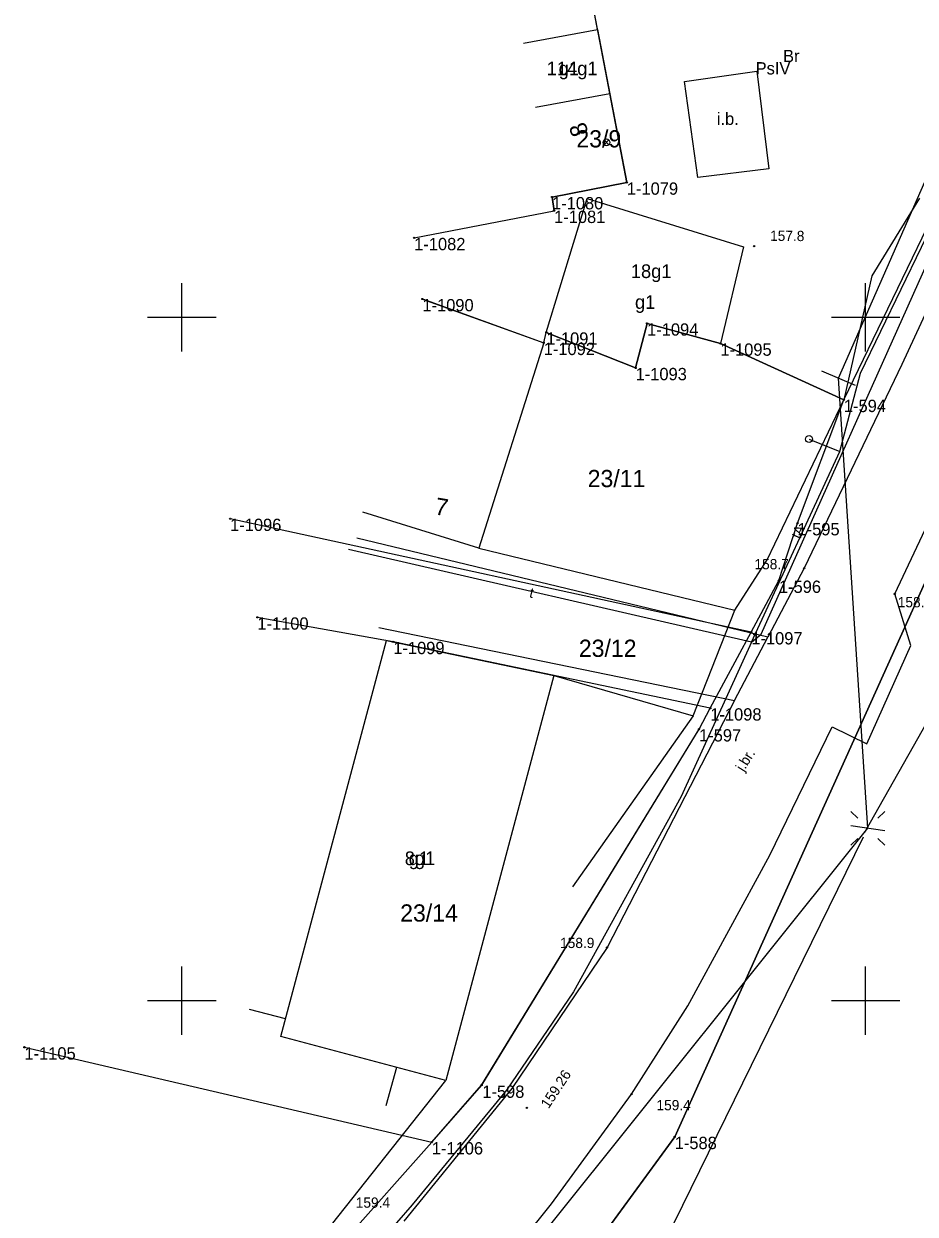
# Model space of a CAD drawing. Extents: x 5598798 to 5599616, y 5661498 to 5662453.
# Drawn here: x 5599088.4 to 5599153.6, y 5661634.4 to 5661721.5 of the extents above; entities that cross this region are included whole.
import ezdxf

# ---------------------------------------------------------------- set-up
doc = ezdxf.new("R2010")
doc.units = 0
for name, color, linetype in [('BUIB_E_T_6', 7, 'Continuous'), ('BUIB_L_1', 7, 'Continuous'), ('BUIB_L_10', 7, 'Continuous'), ('Dzialki', 7, 'Continuous'), ('EADTD_T_0', 7, 'Continuous'), ('EAPADR_T_0', 7, 'Continuous'), ('EGBB_E_T_0', 7, 'Continuous'), ('EGBB_E_T_1', 7, 'Continuous'), ('EGBB_L_0', 7, 'Continuous'), ('Kontury', 7, 'Continuous'), ('KTJZ_E_T_0', 7, 'Continuous'), ('KTJZ_L_0', 7, 'Continuous'), ('KTOK_L_1', 7, 'Continuous'), ('KTOK_L_4', 7, 'Continuous'), ('Numery_dzialek', 7, 'Continuous'), ('Numery_konturow', 7, 'Continuous'), ('Numery_punktow', 7, 'Continuous'), ('Numery_uzytkow', 7, 'Continuous'), ('Podzial_sekcyjny_krzyze', 7, 'Continuous'), ('Punkty', 7, 'Continuous'), ('RTPW_T_0', 7, 'Continuous'), ('RTPW_T_1', 7, 'Continuous'), ('SUPE_L_3', 7, 'Continuous'), ('SUPT_E_T_0', 7, 'Continuous'), ('SUPT_L_0', 7, 'Continuous'), ('SUSM_L_4', 7, 'Continuous'), ('SUSM_T_0', 7, 'Continuous'), ('SUSM_T_3', 7, 'Continuous'), ('Uzytki', 7, 'Continuous')]:
    doc.layers.add(name, color=color, linetype=linetype)

# ---------------------------------------------------------------- blocks, each defined once
blk = doc.blocks.new('GRO')
blk.add_circle((0, 0), 0.045)
blk = doc.blocks.new('1_PADR')
for p, q in [((-0.17675, -0.17675), (0.17675, 0.17675)), ((0.17675, -0.17675), (-0.17675, 0.17675))]:
    blk.add_line(p, q)
blk.add_circle((0, 0), 0.25)
blk = doc.blocks.new('2_RTPW01')
blk.add_circle((0, 0), 0.045)
blk = doc.blocks.new('2_RTPW02')
blk.add_circle((0, 0), 0.045)
blk = doc.blocks.new('4_SUSM01_01')
for p, q in [((-0.74249, 0.74249), (-1.23746, 1.23746)), ((0.74249, 0.74249), (1.23746, 1.23746)), ((-0.74249, -0.74249), (-1.23746, -1.23746)), ((0.74249, -0.74249), (1.23746, -1.23746))]:
    blk.add_line(p, q)
blk = doc.blocks.new('4_SUSM04_01')
blk.add_circle((0, 0), 0.25)

msp = doc.modelspace()

# ---------------------------------------------------------------- linework, layer by layer
at = {"layer": 'BUIB_L_1'}
for p, q in [((5599107.586968, 5661648.68043), (5599104.937907, 5661649.356613)), ((5599115.696576, 5661645.112289), (5599114.918825, 5661642.299391))]:
    msp.add_line(p, q, dxfattribs=at)
at = {"layer": 'BUIB_L_10'}
for p, q in [((5599136.765384, 5661717.245894), (5599142.040119, 5661717.989979)), ((5599137.740962, 5661710.218425), (5599136.765384, 5661717.245894)), ((5599142.040119, 5661717.989979), (5599142.921998, 5661710.852276)), ((5599142.921998, 5661710.852276), (5599137.740962, 5661710.218425)), ((5599149.83, 5661661.97), (5599133.66, 5661629))]:
    msp.add_line(p, q, dxfattribs=at)
at = {"layer": 'Dzialki'}
for p, q in [((5599148.41, 5661693.96), (5599172.35, 5661743.59)), ((5599132.54, 5661709.86), (5599128.89, 5661728.95)), ((5599127.07, 5661708.79), (5599132.54, 5661709.86)), ((5599127.22, 5661707.79), (5599127.07, 5661708.79)), ((5599116.99, 5661705.8), (5599127.22, 5661707.79)), ((5599117.59, 5661701.33), (5599126.46, 5661698.13)), ((5599126.46, 5661698.13), (5599126.65, 5661698.89)), ((5599126.65, 5661698.89), (5599133.18, 5661696.29)), ((5599133.18, 5661696.29), (5599134.02, 5661699.55)), ((5599134.02, 5661699.55), (5599139.38, 5661698.08)), ((5599139.38, 5661698.08), (5599148.41, 5661693.96)), ((5599145.02, 5661684.94), (5599148.41, 5661693.96)), ((5599141.64, 5661676.96), (5599103.53, 5661685.26)), ((5599143.66, 5661680.73), (5599145.02, 5661684.94)), ((5599155.84, 5661683.95), (5599136.04, 5661640.04)), ((5599141.64, 5661676.96), (5599143.66, 5661680.73)), ((5599115.46, 5661676.25), (5599105.52, 5661678.04)), ((5599138.64, 5661671.39), (5599115.46, 5661676.25)), ((5599138.64, 5661671.39), (5599141.64, 5661676.96)), ((5599137.82, 5661669.86), (5599138.64, 5661671.39)), ((5599121.922727, 5661643.823565), (5599137.82, 5661669.86)), ((5599088.49, 5661646.59), (5599118.28, 5661639.65)), ((5599118.28, 5661639.65), (5599121.922727, 5661643.823565)), ((5599106.61, 5661626.54), (5599118.28, 5661639.65)), ((5599136.04, 5661640.04), (5599129.55, 5661631.14))]:
    msp.add_line(p, q, dxfattribs=at)
at = {"layer": 'EGBB_L_0'}
for p, q in [((5599130.402266, 5661721.050548), (5599128.89, 5661728.95)), ((5599124.98595, 5661720.056186), (5599130.402266, 5661721.050548)), ((5599130.402266, 5661721.050548), (5599131.294836, 5661716.348368)), ((5599131.294836, 5661716.348368), (5599125.850628, 5661715.345187)), ((5599131.294836, 5661716.348368), (5599132.54, 5661709.86)), ((5599132.54, 5661709.86), (5599127.07, 5661708.79)), ((5599126.65, 5661698.89), (5599129.644169, 5661708.695065)), ((5599127.07, 5661708.79), (5599127.22, 5661707.79)), ((5599129.644169, 5661708.695065), (5599141.079379, 5661705.157254)), ((5599116.99, 5661705.8), (5599127.22, 5661707.79)), ((5599141.079379, 5661705.157254), (5599139.38, 5661698.08)), ((5599117.593221, 5661701.334271), (5599126.46, 5661698.13)), ((5599133.18, 5661696.29), (5599126.65, 5661698.89)), ((5599134.02, 5661699.55), (5599133.18, 5661696.29)), ((5599139.38, 5661698.08), (5599134.02, 5661699.55)), ((5599126.46, 5661698.13), (5599121.728162, 5661683.10618)), ((5599121.728162, 5661683.10618), (5599113.227989, 5661685.736155)), ((5599107.236944, 5661647.366337), (5599114.955347, 5661676.343468)), ((5599114.955347, 5661676.343468), (5599127.190146, 5661673.791932)), ((5599127.190146, 5661673.791932), (5599119.296241, 5661644.153167)), ((5599119.296241, 5661644.153167), (5599107.236944, 5661647.366337))]:
    msp.add_line(p, q, dxfattribs=at)
at = {"layer": 'Kontury'}
for p, q in [((5599148.41, 5661693.96), (5599172.35, 5661743.59)), ((5599145.02, 5661684.94), (5599148.41, 5661693.96)), ((5599143.66, 5661680.73), (5599145.02, 5661684.94)), ((5599136.04, 5661640.04), (5599155.84, 5661683.95)), ((5599141.64, 5661676.96), (5599143.66, 5661680.73)), ((5599138.64, 5661671.39), (5599141.64, 5661676.96)), ((5599137.82, 5661669.86), (5599138.64, 5661671.39)), ((5599121.922727, 5661643.823565), (5599137.82, 5661669.86)), ((5599118.28, 5661639.65), (5599121.922727, 5661643.823565)), ((5599106.61, 5661626.54), (5599118.28, 5661639.65)), ((5599129.55, 5661631.14), (5599136.04, 5661640.04))]:
    msp.add_line(p, q, dxfattribs=at)
at = {"layer": 'KTJZ_L_0'}
for p, q in [((5599161.82, 5661716.42), (5599152.64, 5661696.54)), ((5599152.13, 5661679.75), (5599161.53, 5661699.74)), ((5599152.64, 5661696.54), (5599145.51, 5661681.63)), ((5599142.85, 5661676.59), (5599112.8, 5661683.84)), ((5599145.51, 5661681.63), (5599142.85, 5661676.59)), ((5599153.3, 5661675.98), (5599152.13, 5661679.75)), ((5599114.41, 5661677.3), (5599140.4, 5661671.95)), ((5599140.4, 5661671.95), (5599142.85, 5661676.59)), ((5599150.08, 5661668.78), (5599153.3, 5661675.98)), ((5599140.4, 5661671.95), (5599131.09, 5661653.89)), ((5599142.99, 5661660.65), (5599147.56, 5661670.04)), ((5599147.56, 5661670.04), (5599150.08, 5661668.78)), ((5599136.99, 5661649.62), (5599142.99, 5661660.65)), ((5599131.09, 5661653.89), (5599124.14, 5661643.58)), ((5599132.88, 5661643.17), (5599136.99, 5661649.62)), ((5599124.14, 5661643.58), (5599116.23, 5661633.87)), ((5599127.02, 5661635.13), (5599132.88, 5661643.17)), ((5599122.86, 5661629.96), (5599127.02, 5661635.13))]:
    msp.add_line(p, q, dxfattribs=at)
at = {"layer": 'KTOK_L_1'}
msp.add_line((5599137.397412, 5661670.82674), (5599140.428869, 5661678.570734), dxfattribs=at)
at = {"layer": 'KTOK_L_4'}
for p, q in [((5599153.946801, 5661708.707327), (5599150.463381, 5661703.019211)), ((5599150.463381, 5661703.019211), (5599148.41, 5661693.96)), ((5599148.41, 5661693.96), (5599139.38, 5661698.08)), ((5599142.812449, 5661682.251695), (5599148.41, 5661693.96)), ((5599121.728162, 5661683.10618), (5599140.428869, 5661678.570734)), ((5599140.428869, 5661678.570734), (5599142.812449, 5661682.251695)), ((5599127.190146, 5661673.791932), (5599137.397412, 5661670.82674)), ((5599137.397412, 5661670.82674), (5599128.555341, 5661658.319499)), ((5599106.208386, 5661627.645012), (5599119.296241, 5661644.153167))]:
    msp.add_line(p, q, dxfattribs=at)
at = {"layer": 'Podzial_sekcyjny_krzyze'}
for p, q in [((5599100, 5661697.5), (5599100, 5661702.5)), ((5599150, 5661697.5), (5599150, 5661702.5)), ((5599097.5, 5661700), (5599102.5, 5661700)), ((5599147.5, 5661700), (5599152.5, 5661700)), ((5599100, 5661647.5), (5599100, 5661652.5)), ((5599150, 5661647.5), (5599150, 5661652.5)), ((5599097.5, 5661650), (5599102.5, 5661650)), ((5599147.5, 5661650), (5599152.5, 5661650))]:
    msp.add_line(p, q, dxfattribs=at)
at = {"layer": 'SUPE_L_3'}
for p, q in [((5599148.021884, 5661695.534034), (5599158.332094, 5661719.064332)), ((5599150.160871, 5661662.612128), (5599148.021884, 5661695.534034)), ((5599160.846586, 5661681.673946), (5599149.92, 5661662.3)), ((5599125.304463, 5661631.572851), (5599150.160871, 5661662.612128))]:
    msp.add_line(p, q, dxfattribs=at)
at = {"layer": 'SUPT_L_0'}
for p, q in [((5599149.624419, 5661695.89561), (5599157.421027, 5661712.050333)), ((5599142.364839, 5661676.801704), (5599155.313425, 5661705.739483)), ((5599148.123603, 5661690.178824), (5599149.624419, 5661695.89561)), ((5599145.861892, 5661691.087872), (5599148.123603, 5661690.178824)), ((5599141.657376, 5661676.235365), (5599148.123603, 5661690.178824)), ((5599141.657376, 5661676.235365), (5599112.179701, 5661683.008901)), ((5599141.657376, 5661676.235365), (5599136.511984, 5661664.923152)), ((5599141.657376, 5661676.235365), (5599142.364839, 5661676.801704)), ((5599136.511984, 5661664.923152), (5599128.632872, 5661650.637436)), ((5599128.632872, 5661650.637436), (5599123.734045, 5661643.442762)), ((5599123.734045, 5661643.442762), (5599116.831229, 5661635.062005)), ((5599116.831229, 5661635.062005), (5599109.40253, 5661626.489212))]:
    msp.add_line(p, q, dxfattribs=at)
at = {"layer": 'SUSM_L_4'}
for p, q in [((5599149.25444, 5661695.006786), (5599146.789329, 5661696.061282)), ((5599151.405583, 5661662.430319), (5599148.916158, 5661662.793938))]:
    msp.add_line(p, q, dxfattribs=at)
at = {"layer": 'Uzytki'}
for p, q in [((5599148.41, 5661693.96), (5599172.35, 5661743.59)), ((5599145.02, 5661684.94), (5599148.41, 5661693.96)), ((5599143.66, 5661680.73), (5599145.02, 5661684.94)), ((5599155.84, 5661683.95), (5599136.04, 5661640.04)), ((5599141.64, 5661676.96), (5599143.66, 5661680.73)), ((5599138.64, 5661671.39), (5599141.64, 5661676.96)), ((5599137.82, 5661669.86), (5599138.64, 5661671.39)), ((5599121.92445, 5661643.821137), (5599137.82, 5661669.86)), ((5599118.28, 5661639.65), (5599121.92445, 5661643.821137)), ((5599106.61, 5661626.54), (5599118.28, 5661639.65)), ((5599136.04, 5661640.04), (5599129.55, 5661631.14))]:
    msp.add_line(p, q, dxfattribs=at)

# ---------------------------------------------------------------- block references
at = {"layer": 'EAPADR_T_0'}
msp.add_blockref('1_PADR', (5599131.051059, 5661712.790397), dxfattribs=at)
at = {"layer": 'Punkty'}
for p in [(5599132.54, 5661709.86), (5599127.07, 5661708.79), (5599127.22, 5661707.79), (5599116.99, 5661705.8), (5599117.59, 5661701.33), (5599126.65, 5661698.89), (5599134.02, 5661699.55), (5599126.46, 5661698.13), (5599139.38, 5661698.08), (5599133.18, 5661696.29), (5599148.41, 5661693.96), (5599103.53, 5661685.26), (5599145.02, 5661684.94), (5599143.66, 5661680.73), (5599105.52, 5661678.04), (5599115.46, 5661676.25), (5599141.64, 5661676.96), (5599138.64, 5661671.39), (5599137.82, 5661669.86), (5599088.49, 5661646.59), (5599121.922727, 5661643.823565), (5599118.28, 5661639.65), (5599136.04, 5661640.04)]:
    msp.add_blockref('GRO', p, dxfattribs=at)
at = {"layer": 'RTPW_T_0'}
msp.add_blockref('2_RTPW01', (5599141.85272, 5661705.202742), dxfattribs=at)
at = {"layer": 'RTPW_T_0', "rotation": -3.0000000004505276e-06}
for p in [(5599145.51, 5661681.63), (5599152.13, 5661679.75), (5599131.09, 5661653.89), (5599132.88, 5661643.17)]:
    msp.add_blockref('2_RTPW01', p, dxfattribs=at)
at = {"layer": 'RTPW_T_1'}
msp.add_blockref('2_RTPW02', (5599125.225593, 5661642.151342), dxfattribs=at)
at = {"layer": 'SUSM_T_0'}
msp.add_blockref('4_SUSM01_01', (5599150.160871, 5661662.612128), dxfattribs=at)
at = {"layer": 'SUSM_T_3'}
msp.add_blockref('4_SUSM04_01', (5599145.861892, 5661691.087872), dxfattribs=at)

# ---------------------------------------------------------------- texts
at = {"layer": 'BUIB_E_T_6'}
msp.add_text('i.b.', height=0.9, dxfattribs=at).set_placement((5599139.118897, 5661714.067583))
at = {"layer": 'EADTD_T_0'}
for s, rotation, p in [('8', 109.473169, (5599129.760226, 5661713.485594)), ('7', 350.537678, (5599118.43953, 5661685.583218))]:
    msp.add_text(s, height=1.25, rotation=rotation, dxfattribs=at).set_placement(p)
at = {"layer": 'EGBB_E_T_0'}
for p in [(5599127.554187, 5661717.700072), (5599133.137045, 5661700.610387), (5599116.588852, 5661659.913726)]:
    msp.add_text('g1', height=1, dxfattribs=at).set_placement(p)
at = {"layer": 'EGBB_E_T_1'}
for s, p in [('114g1', (5599126.68142, 5661717.700072)), ('18g1', (5599132.830658, 5661702.865853)), ('8g1', (5599116.298469, 5661659.913726))]:
    msp.add_text(s, height=1, dxfattribs=at).set_placement(p)
at = {"layer": 'KTJZ_E_T_0'}
msp.add_text('j.br.', height=0.75, rotation=58.200005, dxfattribs=at).set_placement((5599141.081369, 5661666.70452))
at = {"layer": 'Numery_dzialek'}
for s, p in [('23/9', (5599128.849278, 5661712.420465)), ('23/11', (5599129.677359, 5661687.566305)), ('23/12', (5599129.030936, 5661675.150236)), ('23/14', (5599115.965535, 5661655.783764))]:
    msp.add_text(s, height=1.26, dxfattribs=at).set_placement(p)
at = {"layer": 'Numery_konturow'}
msp.add_text('PsIV', height=0.9, dxfattribs=at).set_placement((5599141.957521, 5661717.757671))
at = {"layer": 'Numery_punktow'}
for s, p in [('1-1079', (5599132.54, 5661708.96)), ('1-1080', (5599127.07, 5661707.89)), ('1-1081', (5599127.22, 5661706.89)), ('1-1082', (5599116.99, 5661704.9)), ('1-1090', (5599117.59, 5661700.43)), ('1-1091', (5599126.65, 5661697.99)), ('1-1094', (5599134.02, 5661698.65)), ('1-1092', (5599126.46, 5661697.23)), ('1-1095', (5599139.38, 5661697.18)), ('1-1093', (5599133.18, 5661695.39)), ('1-594', (5599148.41, 5661693.06)), ('1-1096', (5599103.53, 5661684.36)), ('1-595', (5599145.02, 5661684.04)), ('1-596', (5599143.66, 5661679.83)), ('1-1100', (5599105.52, 5661677.14)), ('1-1099', (5599115.46, 5661675.35)), ('1-1097', (5599141.64, 5661676.06)), ('1-1098', (5599138.64, 5661670.49)), ('1-597', (5599137.82, 5661668.96)), ('1-1105', (5599088.49, 5661645.69)), ('1-598', (5599121.97, 5661642.89)), ('1-1106', (5599118.28, 5661638.75)), ('1-588', (5599136.04, 5661639.14))]:
    msp.add_text(s, height=0.9, dxfattribs=at).set_placement(p)
at = {"layer": 'Numery_uzytkow'}
msp.add_text('Br', height=0.9, dxfattribs=at).set_placement((5599143.961869, 5661718.657671))
at = {"layer": 'RTPW_T_0'}
msp.add_text('157.8', height=0.75, rotation=359.474365, dxfattribs=at).set_placement((5599143.010186, 5661705.588564))
for s, p in [('158.7', (5599141.871324, 5661681.558284)), ('158.8', (5599152.35, 5661678.78)), ('158.9', (5599127.656986, 5661653.849065)), ('159.4', (5599134.705135, 5661641.980368)), ('159.4', (5599112.716168, 5661634.85117))]:
    msp.add_text(s, height=0.75, dxfattribs=at).set_placement(p)
at = {"layer": 'RTPW_T_1'}
msp.add_text('159.26', height=0.75, rotation=56.659305, dxfattribs=at).set_placement((5599126.817967, 5661642.051819))
at = {"layer": 'SUPT_E_T_0'}
for s, rotation, p in [('tA', 66.71001, (5599145.214163, 5661683.721241)), ('t', 347.05892, (5599125.366902, 5661679.51261))]:
    msp.add_text(s, height=0.75, rotation=rotation, dxfattribs=at).set_placement(p)

doc.saveas('drawing.dxf')
